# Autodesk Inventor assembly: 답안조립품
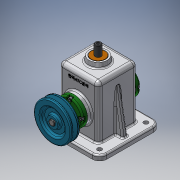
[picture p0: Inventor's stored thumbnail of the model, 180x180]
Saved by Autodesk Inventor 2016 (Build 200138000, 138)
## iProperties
Created: 2022-11
Part Number: 답안조립품
Material: 일반
Document SubType Name: Assembly
Designer: CAD2
Author: CAD2
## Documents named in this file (16)
- C:\Users\CAD2\Desktop\721106V1010\답안조립품.iam
- C:\Users\CAD2\Desktop\721106V1010\본체.ipt
- C:\Users\CAD2\Desktop\721106V1010\앞커버.ipt
- C:\Users\CAD2\Desktop\721106V1010\뒤커버.ipt
- C:\Users\CAD2\Desktop\721106V1010\베어링 6201.ipt
- C:\Users\CAD2\Desktop\721106V1010\오일실 12 25 7.ipt
- C:\Users\CAD2\Desktop\721106V1010\편심축.ipt
- C:\Users\CAD2\Desktop\721106V1010\키 4 x 4 x 15.ipt
- C:\Users\CAD2\Desktop\721106V1010\멈춤나사 M3 x 8.ipt
- C:\Users\CAD2\Desktop\721106V1010\V벨트풀리.ipt
- C:\Users\CAD2\Desktop\721106V1010\링크.ipt
- C:\Users\CAD2\Desktop\721106V1010\슬라이드.ipt
- C:\Users\CAD2\Desktop\721106V1010\핀 5 x 18.ipt
- C:\Users\CAD2\Desktop\721106V1010\부시.ipt
- C:\Users\CAD2\Desktop\721106V1010\고정핀 1.2 x 10.ipt
- C:\Users\CAD2\Desktop\721106V1010\볼트 M4 x 12.ipt
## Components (11 placed, 4 different names)
1. V벨트풀리:1
2. 핀 5 x 18:1
3. 고정핀 1.2 x 10:1
4. ISO 4762 M4 x 12:1
5. ISO 4762 M4 x 12:2
6. ISO 4762 M4 x 12:3
7. ISO 4762 M4 x 12:4
8. ISO 4762 M4 x 12:5
9. ISO 4762 M4 x 12:6
10. ISO 4762 M4 x 12:7
11. ISO 4762 M4 x 12:8
